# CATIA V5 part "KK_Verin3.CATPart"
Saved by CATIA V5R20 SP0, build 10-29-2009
Part number: Verin3
Bounding box of the stored display mesh (mm): x 71.66 to 104.997, y -13.406 to 5.333, z -5 to 66.399
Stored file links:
  G:\Khaled_CFAO_2011\ST2M\ST2M_GR1\msallin\Khaled\Version_Finale\KK_Verin3.CATPart
  C:\Users\Mathieu\Desktop\Think Motion\JOUG-MELEE2.CATProduct
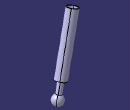
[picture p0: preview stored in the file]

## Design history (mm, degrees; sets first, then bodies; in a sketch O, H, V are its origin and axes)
External parameters (linked from other documents)
  `External.Taille du joug` = 100 mm
Set1
  Line1: linked copy from another document
  Line2: linked copy from another document
  Point1: linked copy from another document
Set2
  Plane1: type 2Lines, Element1 Line1, Element2 Line2
  Plane2: type 2Lines, Element1 Sketch1.L5, Element2 Sketch1.L3
  Point2: type Center, Curve Sketch1
  DatumSurface1
Body1 (main body)
  Sketch1 on Plane1, origin (70.7263, -40.514, 20.3771), H (-0.4971, -0.8677, 0), V (-0.2105, 0.1206, 0.9701)
    line L1 (-51.1904, -16.148) -> (-48.3959, -6.5464)
    line L2 (-48.3959, -6.5464) -> (-50.7963, -5.8477)
    line L3 (-50.7963, -5.8477) -> (-35.4266, 46.9611)
    line L4 (-35.4266, 46.9611) -> (-34.6265, 46.7282)
    line L5 (-34.6265, 46.7282) -> (-46.9222, 4.4812)
    line L6 (-46.9222, 4.4812) -> (-42.9216, 3.3168)
    point P7 (-42.9216, 3.3168)
    arc A1 centre (-50, -21.0042) radius 5 from (-51.1904, -16.148) to (-51.3972, -25.805) ccw
    point P8 (-50, -21.0042)
    point P9 (-51.3972, -25.805)
    reference projected line E1 (-20, 82.0734) -> (-50, -21.0042) from Line1
    reference projected line E2 (-20, 82.0734) -> (-50, -21.0042) from Line1
    reference projected line E3 (-20, 82.0734) -> (-50, -21.0042) from Line1
    reference projected point E4 (-50, -21.0042) from Point1
    reference projected line E5 (-20, 82.0734) -> (-50, -21.0042) from Line1
    length L3 = 55 {= `External.Taille du joug` *(7/10-1/10-1/20)}
    length L5 = 44 {= Sketch1.length(L3) *4/5}
    distance L3 E1 = 5 {= `External.Taille du joug` /20}
    distance L5 E2 = 4.1667 {= `External.Taille du joug` /24}
    distance P7 E3 = 0
    length L2 = 2.5 {= `External.Taille du joug` /40}
    length L1 = 10 {= `External.Taille du joug` /10}
    radius A1 = 5 {= `External.Taille du joug` /20}
    distance P8 E4 = 0
    distance P9 E5 = 0
    perpendicularity: L2 L1
    parallelism: L3 L1, L4 L2, L5 L3, L6 L2
  Shaft1: profile Sketch1, axis Line1, angle 360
